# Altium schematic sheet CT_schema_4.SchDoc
size 556 x 419 mm
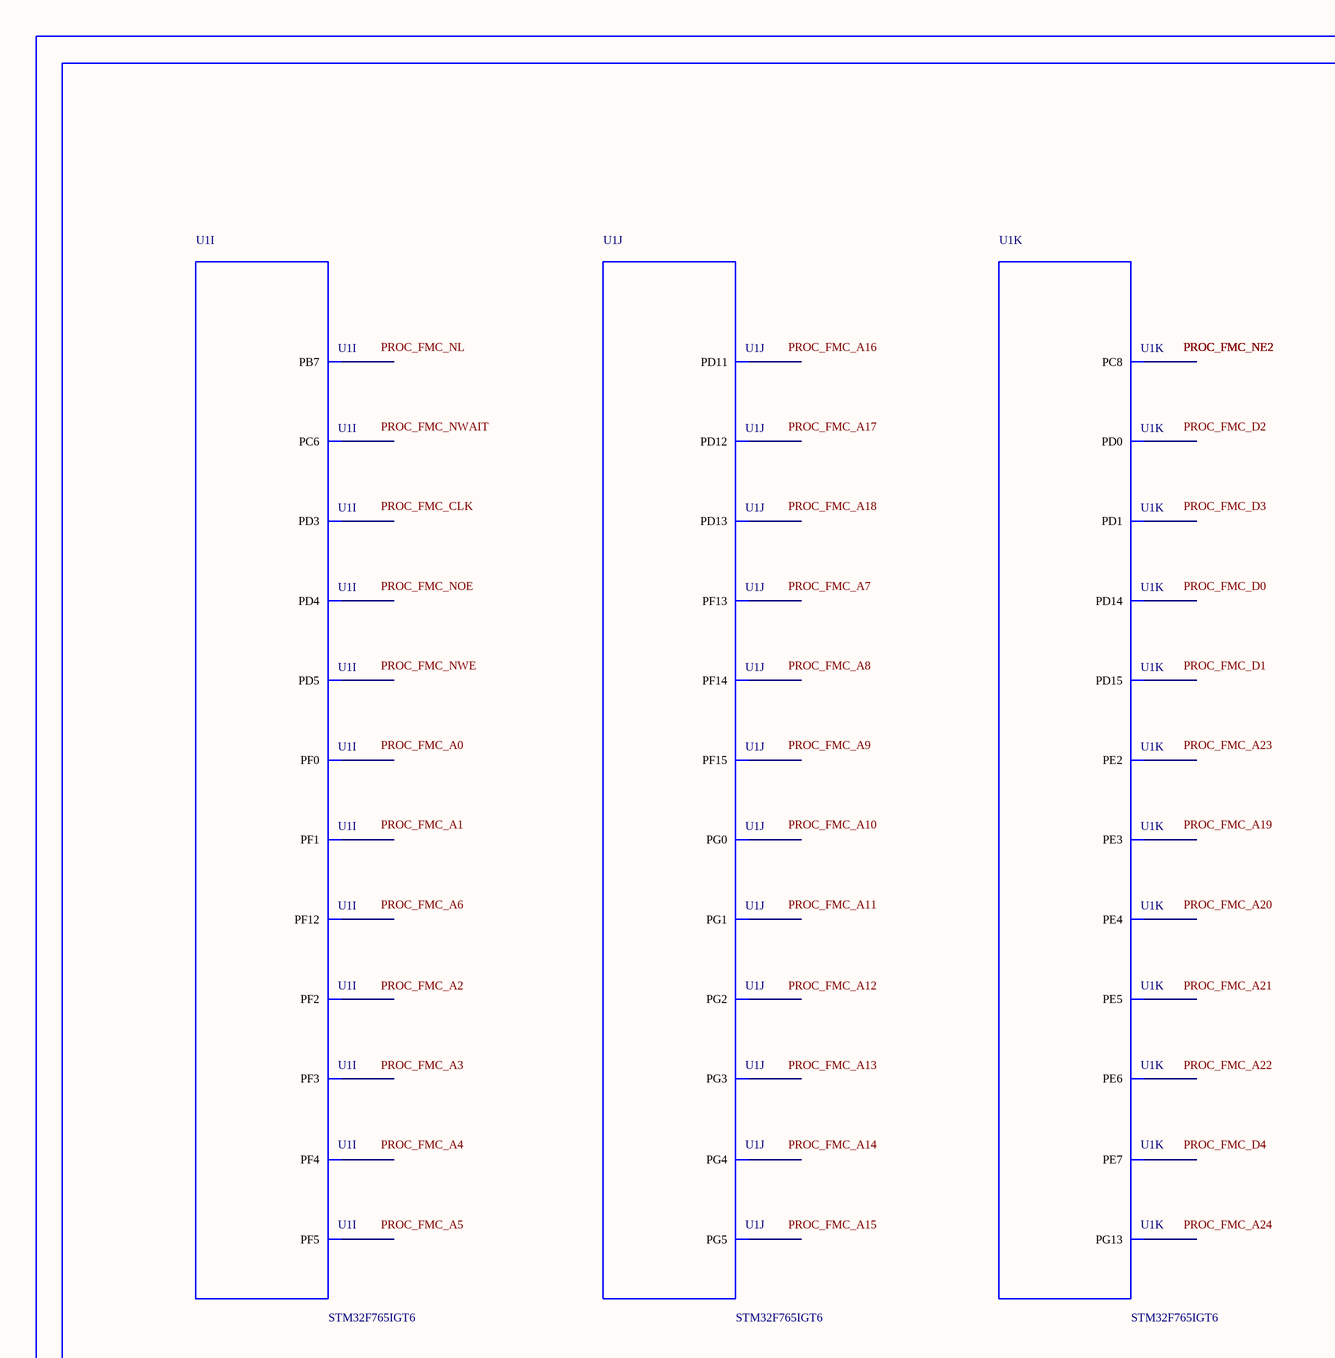
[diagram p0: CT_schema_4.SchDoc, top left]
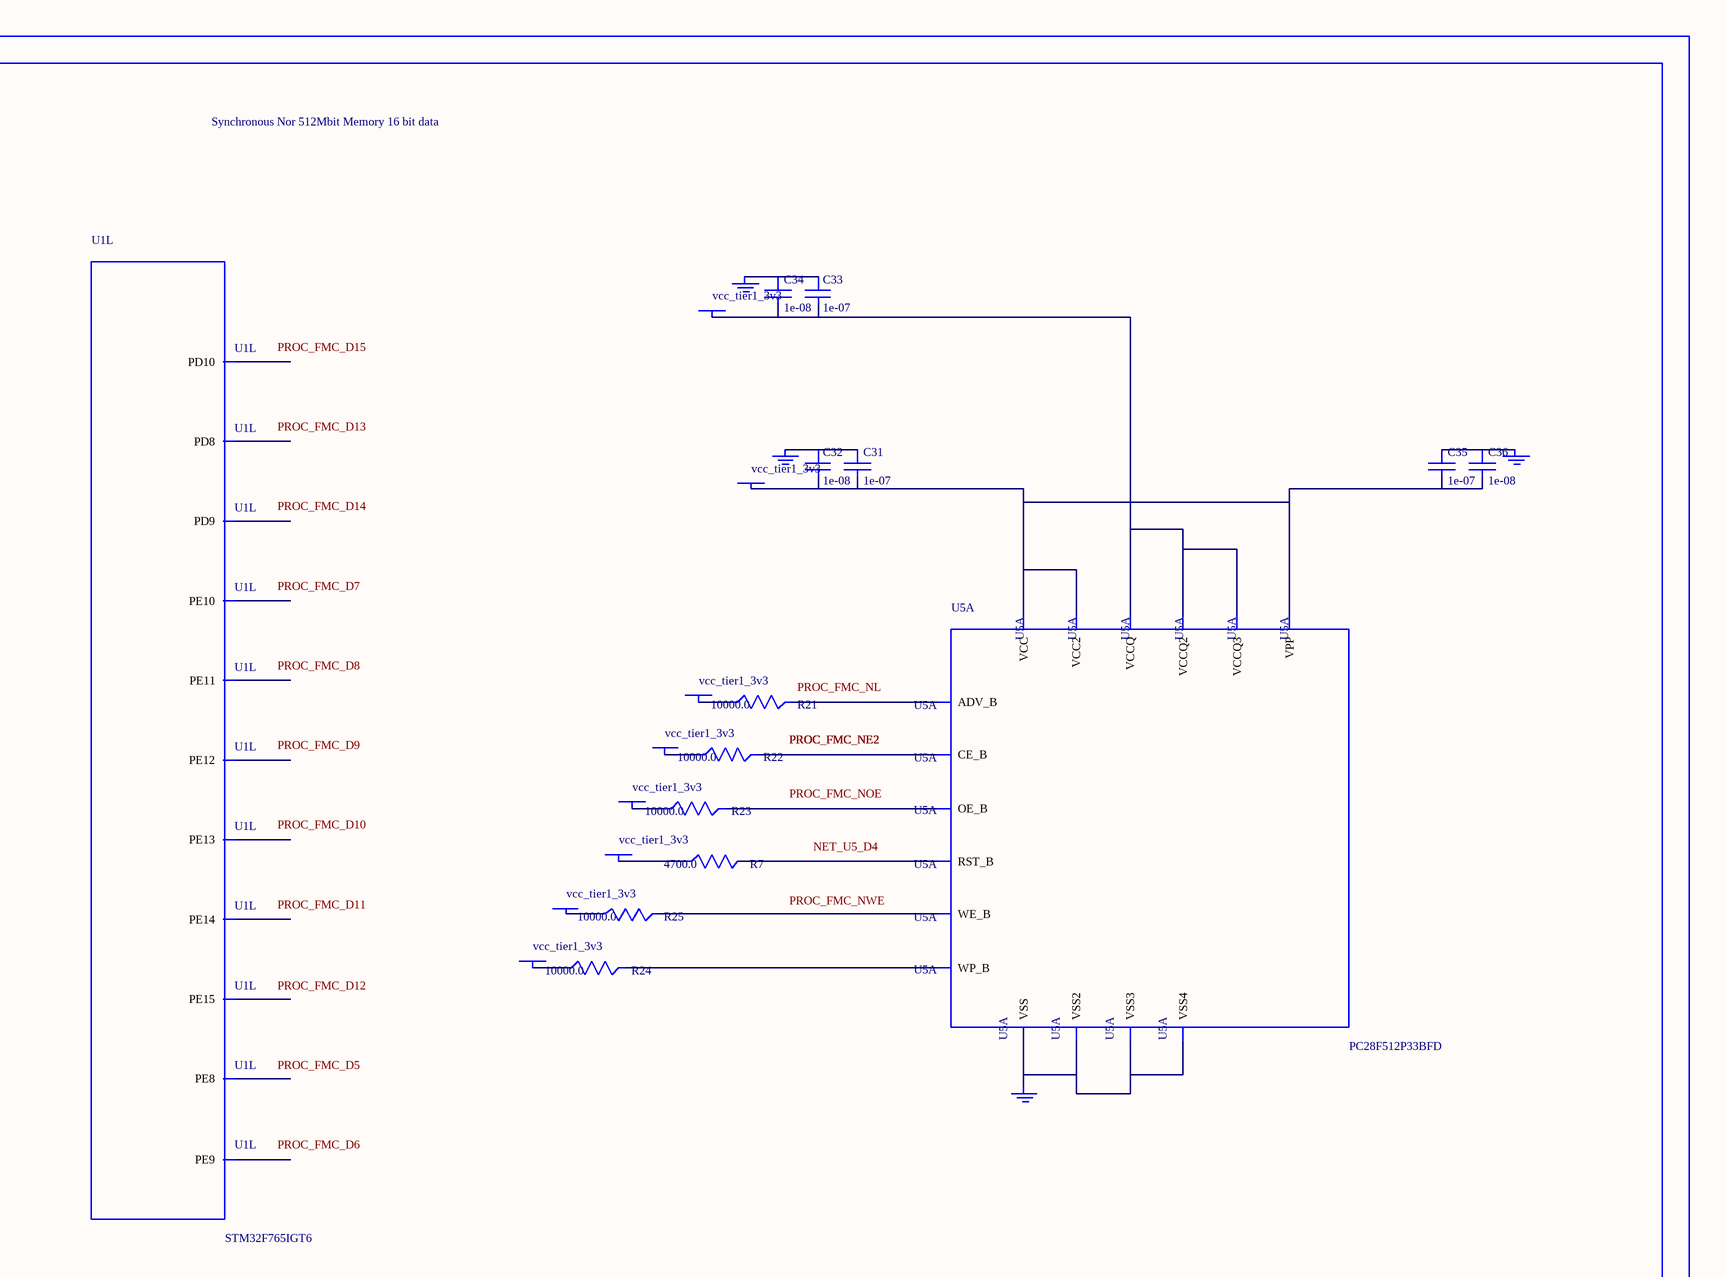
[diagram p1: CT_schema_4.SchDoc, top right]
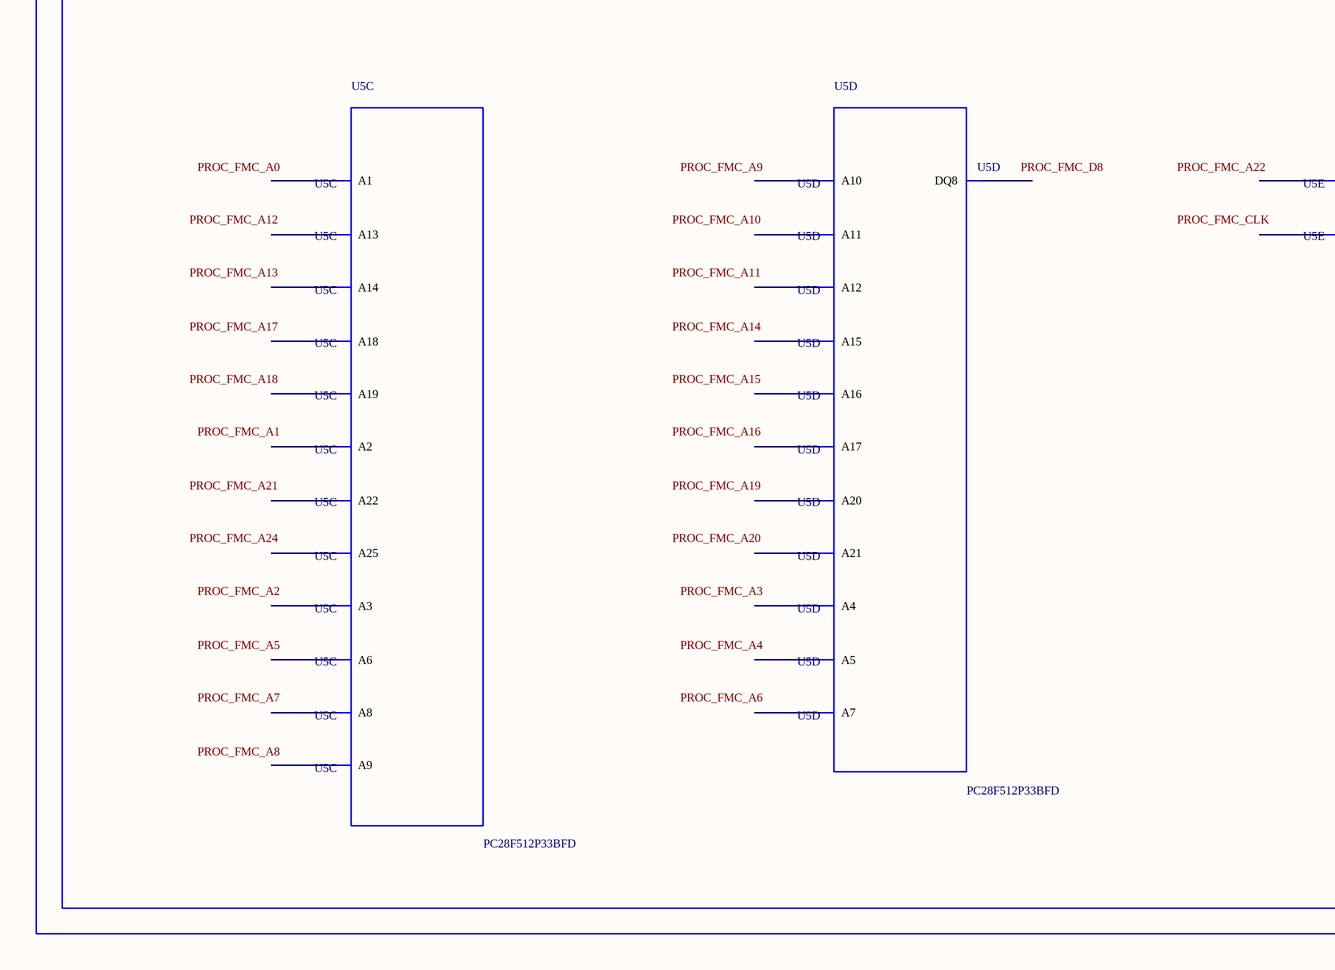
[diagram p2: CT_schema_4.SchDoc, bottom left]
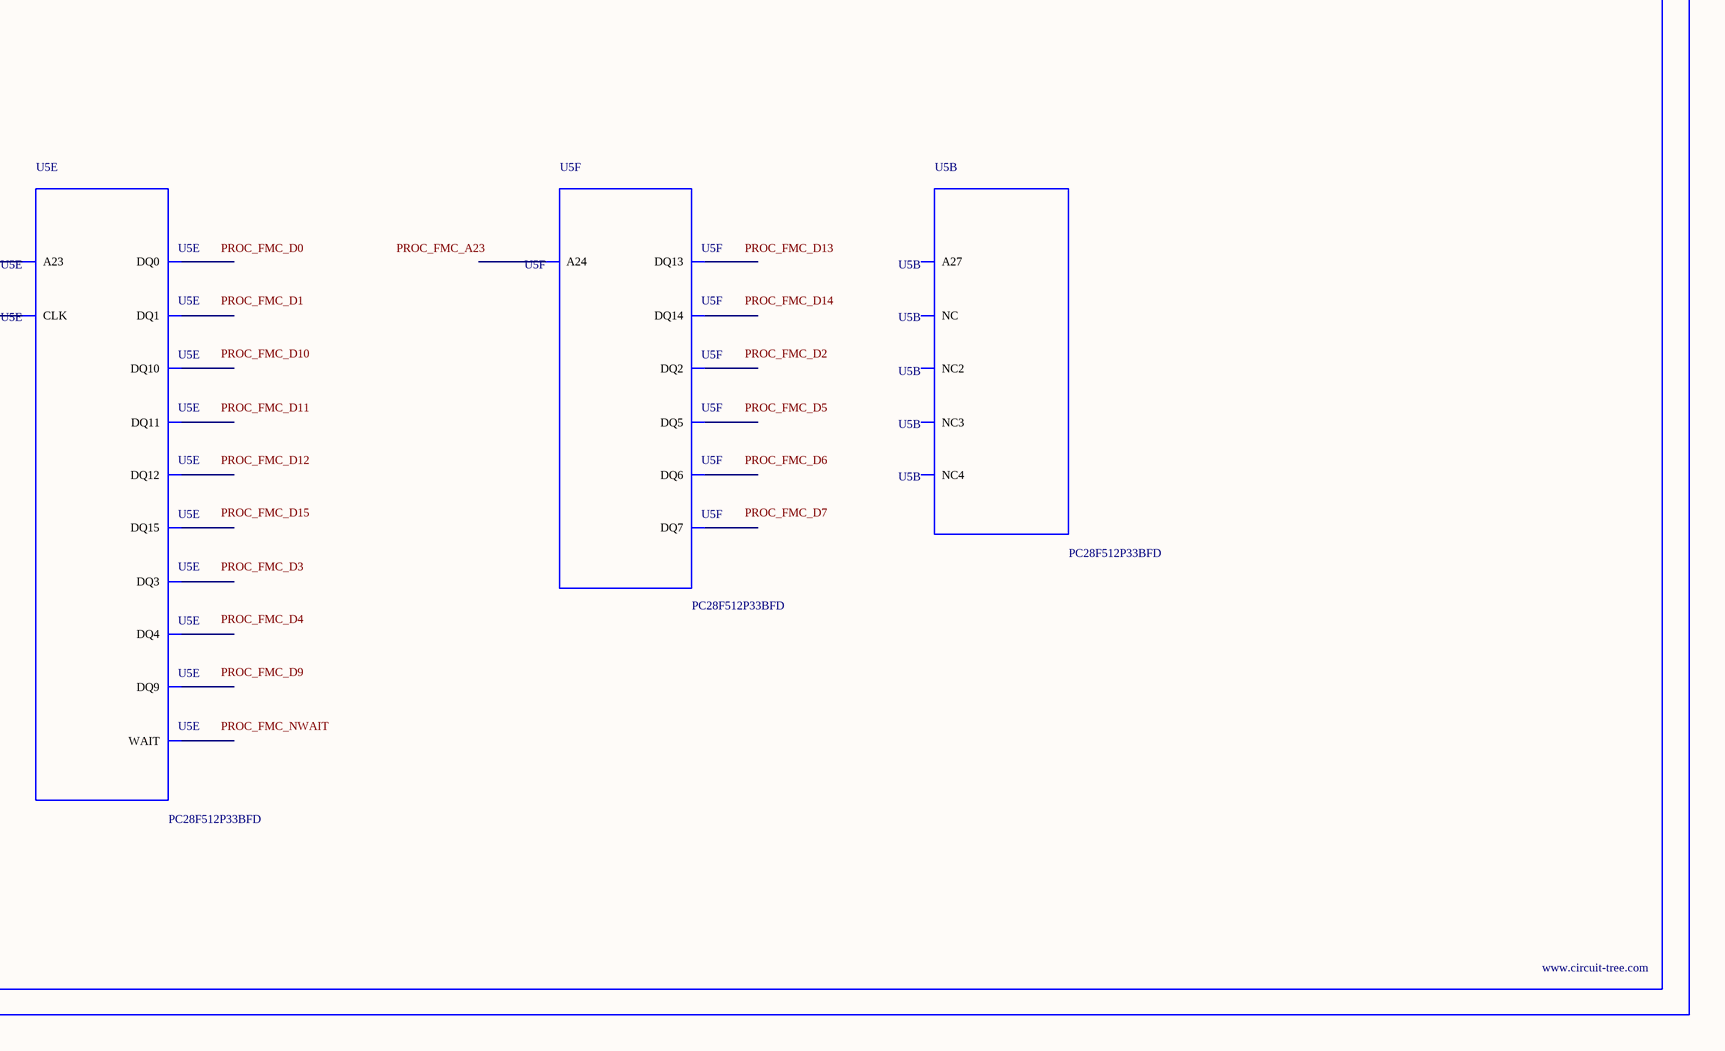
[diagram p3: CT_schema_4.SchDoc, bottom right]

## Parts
BORDER3  (no value)
C31  1e-07  [C0402]
C32  1e-08  [C0402]
C33  1e-07  [C0402]
C34  1e-08  [C0402]
C35  1e-07  [C0402]
C36  1e-08  [C0402]
GND_INSTANCE_3_0  (no value)
GND_INSTANCE_3_1  (no value)
GND_INSTANCE_3_2  (no value)
GND_INSTANCE_3_3  (no value)
POWER_INSTANCE_3_0  vcc_tier1_3v3
POWER_INSTANCE_3_1  vcc_tier1_3v3
POWER_INSTANCE_3_2  vcc_tier1_3v3
POWER_INSTANCE_3_3  vcc_tier1_3v3
POWER_INSTANCE_3_4  vcc_tier1_3v3
POWER_INSTANCE_3_5  vcc_tier1_3v3
POWER_INSTANCE_3_6  vcc_tier1_3v3
POWER_INSTANCE_3_7  vcc_tier1_3v3
R7  4700.0  [R0603]
R21  10000.0  [R0603]
R22  10000.0  [R0603]
R23  10000.0  [R0603]
R24  10000.0  [R0603]
R25  10000.0  [R0603]
U1  STM32F765IGT6  [LQFP176]  (parts I,J,K,L of 14)
U5  PC28F512P33BFD  [PC28F512P33BFD]  (parts A,B,C,D,E,F of 6)

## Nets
NetC31_1: C31.1 C32.1 GND_INSTANCE_3_0.0(GND)
NetC31_2: C31.2 C32.2 C35.2 C36.2 POWER_INSTANCE_3_0.0(PWR) U5.A4(VPP) U5.A6(VCC) U5.H3(VCC2)
NetC33_1: C33.1 C34.1 GND_INSTANCE_3_1.0(GND)
NetC33_2: C33.2 C34.2 POWER_INSTANCE_3_1.0(PWR) U5.D5(VCCQ) U5.D6(VCCQ2) U5.G4(VCCQ3)
NetC35_1: C35.1 C36.1 GND_INSTANCE_3_2.0(GND)
NetGND_INSTANCE_3_3_0: GND_INSTANCE_3_3.0(GND) U5.B2(VSS) U5.H2(VSS2) U5.H4(VSS3) U5.H6(VSS4)
NetPOWER_INSTANCE_3_2_0: POWER_INSTANCE_3_2.0(PWR) R21.1
NetPOWER_INSTANCE_3_3_0: POWER_INSTANCE_3_3.0(PWR) R22.1
NetPOWER_INSTANCE_3_4_0: POWER_INSTANCE_3_4.0(PWR) R23.1
NetPOWER_INSTANCE_3_5_0: POWER_INSTANCE_3_5.0(PWR) R24.1
NetPOWER_INSTANCE_3_6_0: POWER_INSTANCE_3_6.0(PWR) R25.1
NetPOWER_INSTANCE_3_7_0: POWER_INSTANCE_3_7.0(PWR) R7.1
NetR7_2: R7.2 U5.D4(RST_B)
NetR21_2: R21.2 U5.F6(ADV_B)
NetR22_2: R22.2 U5.B4(CE_B)
NetR23_2: R23.2 U5.F8(OE_B)
NetR24_2: R24.2 U5.C6(WP_B)
NetR25_2: R25.2 U5.G8(WE_B)

Not connected (* = marked no-connect by the designer): U1 1(PE2) 2(PE3) 3(PE4) 4(PE5) 5(PE6) 16(PF0) 17(PF1) 18(PF2) 19(PF3) 20(PF4) 21(PF5) 60(PF12) 63(PF13) 64(PF14) 65(PF15) 66(PG0) 67(PG1) 68(PE7) 69(PE8) 70(PE9) 73(PE10) 74(PE11) 75(PE12) 76(PE13) 77(PE14) 78(PE15) 96(PD8) 97(PD9) 98(PD10) 99(PD11) 100(PD12) 101(PD13) 104(PD14) 105(PD15) 106(PG2) 107(PG3) 108(PG4) 109(PG5) 115(PC6) 117(PC8) 142(PD0) 143(PD1) 145(PD3) 146(PD4) 147(PD5) 156(PG13) 165(PB7); U5 A1 A2(A6) A3(A8) A5(A13) A7(A18) A8(A22) B1(A2) B3(A9) B5(A14) B6(A25) B7(A19) B8(NC) C1(A3) C2(A7) C3(A10) C4(A12) C5(A15) C7(A20) C8(A21) D1(A4) D2(A5) D3(A11) D7(A16) D8(A17) E1(DQ8) E2(DQ1) E3(DQ9) E4(DQ3) E5(DQ4) E6(CLK) E7(DQ15) E8(NC2) F1(NC3) F2(DQ0) F3(DQ10) F4(DQ11) F5(DQ12) F7(WAIT) G1(A23) G2(NC4) G3(DQ2) G5(DQ5) G6(DQ6) G7(DQ14) H1(A27) H5(DQ13) H7(DQ7) H8(A24)

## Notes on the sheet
- Labels drawn without touching a wire or pin: NET_U5_D4, PROC_FMC_A0, PROC_FMC_A1, PROC_FMC_A2, PROC_FMC_A3, PROC_FMC_A4, PROC_FMC_A5, PROC_FMC_A6, PROC_FMC_A7, PROC_FMC_A8, PROC_FMC_A9, PROC_FMC_A10, PROC_FMC_A11, PROC_FMC_A12, PROC_FMC_A13, PROC_FMC_A14, PROC_FMC_A15, PROC_FMC_A16, PROC_FMC_A17, PROC_FMC_A18, PROC_FMC_A19, PROC_FMC_A20, PROC_FMC_A21, PROC_FMC_A22, PROC_FMC_A23, PROC_FMC_A24, PROC_FMC_CLK, PROC_FMC_D0, PROC_FMC_D1, PROC_FMC_D2, PROC_FMC_D3, PROC_FMC_D4, PROC_FMC_D5, PROC_FMC_D6, PROC_FMC_D7, PROC_FMC_D8, PROC_FMC_D9, PROC_FMC_D10, PROC_FMC_D11, PROC_FMC_D12, PROC_FMC_D13, PROC_FMC_D14, PROC_FMC_D15, PROC_FMC_NL, PROC_FMC_NOE, PROC_FMC_NWAIT, PROC_FMC_NWE

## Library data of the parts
BORDER3 = BORDER_PAGE3
C31 C33 C35 = C0402C104K3RACTU
C32 C34 C36 = C0402C103K3RAC
GND_INSTANCE_3_0-GND_INSTANCE_3_3 = GND
POWER_INSTANCE_3_0-POWER_INSTANCE_3_7 = PWR
R7 = RC0603JR-074K7L
R21-R25 = RC0603JR-0710KL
